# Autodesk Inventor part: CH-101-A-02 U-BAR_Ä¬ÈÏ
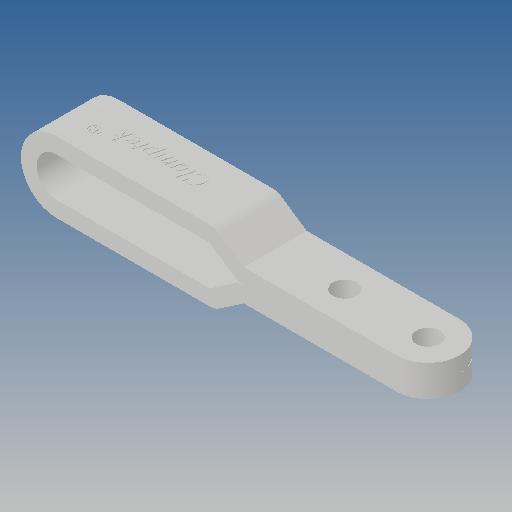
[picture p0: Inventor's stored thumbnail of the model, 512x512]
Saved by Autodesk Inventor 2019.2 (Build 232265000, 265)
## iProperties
Created: 2010-06
Part Number: CH-101-A-02 U-BAR_Ä¬ÈÏ
Material: Ogólny
Document SubType Name: Modeling
Designer: CADENGINEERING4
Density: 1 g/cm^3
Appearance: Domyślna
Author: CADENGINEERING4
Revision Number: ÈÎºÎ
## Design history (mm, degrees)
feature "NONE"
feature "NONE:1"
node "Bryła1"
node "Bryła2"
